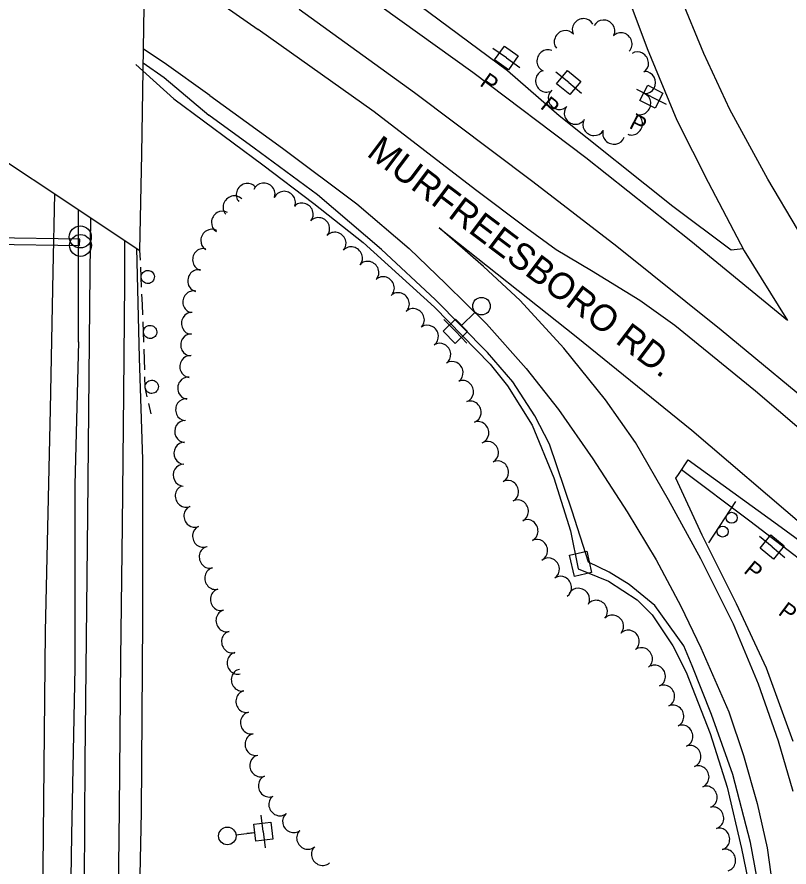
# Model space of a CAD drawing. Extents: x 1746010 to 1754829, y 655801 to 663091.
# Drawn here: x 1754024.1 to 1754375.7, y 656843.1 to 657230 of the extents above; entities that cross this region are included whole.
import ezdxf

# ---------------------------------------------------------------- set-up
doc = ezdxf.new("R2010")
doc.units = 0
for name, color, linetype in [('SURVEY - AERIAL SURVEY - Photo Control - Points - Elevations', 7, 'Continuous'), ('SURVEY - AERIAL SURVEY - Photo Control - Points - Locators', 7, 'Continuous'), ('SURVEY - AERIAL SURVEY - Photo Control - Points - Numbers', 7, 'Continuous'), ('SURVEY - AERIAL SURVEY - Photo Control with Text', 7, 'Continuous'), ('SURVEY - CENTERLINE - Existing Roads Curve Text', 7, 'Continuous'), ('SURVEY - CENTERLINE - Existing Roads Text', 7, 'Continuous'), ('SURVEY - CENTERLINE - Preliminary - Development', 7, 'Continuous'), ('SURVEY - CONTROL - Points - Numbers', 7, 'Continuous')]:
    doc.layers.add(name, color=color, linetype=linetype)

msp = doc.modelspace()

# ---------------------------------------------------------------- linework, layer by layer
at = {"layer": 'SURVEY - AERIAL SURVEY - Photo Control - Points - Elevations'}
for points in [[(1753982.28, 657188.73), (1754080.08, 657123.8), (1754080.93, 657167.72), (1754082.29, 657253.87), (1754084.25, 657323.66), (1754089.74, 657391.89), (1753986.12, 657458.37), (1753985.99, 657391.93), (1753985.12, 657295.57), (1753983.31, 657231.76)], [(1754078.21, 657208.42), (1754095.56, 657192.76), (1754136.12, 657162.67), (1754159.26, 657145.17), (1754181.77, 657127.3), (1754214.2, 657097.87), (1754239.57, 657071.91), (1754247.5, 657062.04), (1754258.73, 657044.18), (1754268.66, 657020.17), (1754276.25, 656996.14), (1754279.63, 656978.75), (1754293.47, 656973.17), (1754306.53, 656964.61), (1754313.35, 656957.81), (1754322.84, 656943.81), (1754328.89, 656931.68), (1754339.84, 656903.89), (1754347.52, 656879.41), (1754354.05, 656851.4), (1754358.17, 656831.58)]]:
    msp.add_lwpolyline(points, dxfattribs=at)
at = {"layer": 'SURVEY - AERIAL SURVEY - Photo Control - Points - Locators'}
for points in [[(1754263.31, 657432.04), (1754270.04, 657378.87), (1754276.75, 657338.19), (1754283.72, 657305.83), (1754290.96, 657277.73), (1754300.49, 657244.28), (1754311.09, 657215.71), (1754324.64, 657183.1), (1754338.91, 657154.83), (1754355.31, 657123.62), (1754374.99, 657091.81), (1754330.98, 657128), (1754283.23, 657165.86), (1754231.77, 657204.81), (1754165.2, 657252.52)], [(1754170.11, 657262.81), (1754207.54, 657235.31), (1754247.49, 657205.62), (1754270.97, 657185.18), (1754322.72, 657143.88), (1754349.35, 657124.09), (1754354.76, 657124.68)], [(1754082.46, 657259.82), (1754102.35, 657246.49), (1754133.89, 657224.33)], [(1754379.5, 657133.43), (1754366.03, 657156.16), (1754348.69, 657187.98), (1754336.85, 657213.49), (1754326.17, 657239.6)], [(1754152.65, 657233.59), (1754205.11, 657195.65), (1754259.01, 657155.1), (1754297.29, 657125.77), (1754344.85, 657087.64), (1754394.72, 657046.26)], [(1754410.66, 657016.7), (1754360.46, 657059.65), (1754323.71, 657089.53), (1754307.82, 657100.92), (1754285.78, 657114.4), (1754269.68, 657123.99), (1754256.08, 657133.86), (1754232.85, 657151.41), (1754186.79, 657186.82), (1754133.89, 657224.33)], [(1754111.99, 657194.33), (1754091.08, 657209.09), (1754081.68, 657215.46)], [(1754081.58, 657209.17), (1754091.13, 657202.56), (1754111.46, 657185.38)], [(1754111.99, 657194.33), (1754145.1, 657170.34), (1754178.83, 657144.95), (1754202.75, 657124.63), (1754219.4, 657108.51), (1754237.98, 657090.35), (1754255.95, 657070.08), (1754270.69, 657051.34), (1754286.3, 657028.95), (1754301.94, 657004.81), (1754315.13, 656982.84), (1754326.39, 656961.76), (1754335.58, 656942.8), (1754348.3, 656913.62), (1754354.99, 656893.8), (1754361.15, 656872.01), (1754365.7, 656851.85), (1754368.96, 656828.87)], [(1754362.13, 656832.88), (1754358.18, 656854.14), (1754350.09, 656885.11), (1754340.4, 656912.46), (1754331.57, 656934.59), (1754327.8, 656943.67), (1754314.58, 656962.06), (1754302.96, 656971.62), (1754293.8, 656977.24), (1754284.39, 656981.85), (1754276.99, 657004.98), (1754266.65, 657035.49), (1754259.96, 657048.43), (1754249.92, 657063.95), (1754238.45, 657077.31), (1754214.63, 657101.48), (1754190.18, 657124.12), (1754161.03, 657149.06), (1754132.18, 657170.31), (1754111.46, 657185.38)], [(1754040.61, 657114.04), (1754041.29, 657149.55)], [(1754057.59, 657138.73), (1754057.29, 657113.76)], [(1754377.63, 656877.42), (1754370.87, 656900.37), (1754361.76, 656926.22), (1754350.36, 656953.57), (1754335.54, 656983.36), (1754320.74, 657010.23), (1754305.77, 657036.26), (1754292.05, 657055.67), (1754273.16, 657079.25), (1754253.25, 657100.99), (1754236.52, 657116.39), (1754216.42, 657134.01), (1754278.8, 657084.62), (1754331.51, 657041.97), (1754382.56, 656998.27)], [(1754073.23, 657109.18), (1754073.22, 657128.35)], [(1754078.6, 657124.78), (1754079.69, 657074.82), (1754081.31, 657028.64), (1754081.24, 656955.57), (1754080.66, 656868.05), (1754078.89, 656781.7)], [(1754031.14, 655808.13), (1754031.3, 655908.75), (1754031.72, 656028.9), (1754031.37, 656137), (1754031.54, 656254.42), (1754031.6, 656339.87), (1754031.41, 656445.55), (1754032.12, 656538.49), (1754033.45, 656650.9), (1754034.71, 656754.09), (1754036.08, 656842.73), (1754037.13, 656950.3), (1754039.4, 657051.48), (1754040.61, 657114.04)], [(1754057.29, 657113.76), (1754056.29, 657003.36), (1754055.05, 656891.08), (1754054.38, 656780.56)], [(1754070.25, 656818.01), (1754070.75, 656869.41), (1754071.43, 656937.85), (1754072.17, 656998.74), (1754072.78, 657058.55), (1754073.23, 657109.18)], [(1754325.34, 657021.8), (1754329.84, 657028.37), (1754370.47, 656999.02), (1754411.6, 656968.94), (1754464.49, 656922.99), (1754497.74, 656893.4)], [(1754377.64, 656900.23), (1754365.43, 656933.5), (1754351.81, 656962.84), (1754336.15, 656994.11), (1754324.18, 657020.03), (1754325.34, 657021.8)], [(1754488.29, 656855.97), (1754482.85, 656857.89), (1754490.99, 656890.46), (1754437.5, 656937.58), (1754399.88, 656968.26), (1754357.83, 657000.5), (1754326.71, 657023.81)]]:
    msp.add_lwpolyline(points, dxfattribs=at)
at = {"layer": 'SURVEY - AERIAL SURVEY - Photo Control - Points - Numbers'}
for points in [[(1754052.19, 657082.05), (1754052.08, 657142.39)], [(1754080.3, 657119.38), (1754080.08, 657123.85)], [(1754080.89, 657106.99), (1754080.45, 657116.18)], [(1754081.27, 657099.1), (1754081.04, 657103.79)], [(1754081.5, 657094.4), (1754081.27, 657099.1)], [(1754081.91, 657082.01), (1754081.65, 657091.21)], [(1754052.19, 657082.1), (1754050.4, 657016.97), (1754050.41, 656933.95), (1754048.92, 656857.56), (1754047.62, 656769.57), (1754047.63, 656692.19), (1754047.02, 656648.26), (1754045.2, 656574.61), (1754044.51, 656529.38), (1754044.63, 656444.15), (1754044.94, 656375.53), (1754044.42, 656301.79), (1754044.34, 656224.86), (1754044.22, 656141.35), (1754043.78, 656087.01), (1754044.06, 656016.26), (1754043.35, 655955.88), (1754042, 655902.52), (1754042.42, 655813.6), (1754042.39, 655808.41)], [(1754082.14, 657074.11), (1754082, 657078.81)], [(1754082.27, 657069.41), (1754082.14, 657074.11)], [(1754083.46, 657057.12), (1754082.5, 657061.31), (1754082.36, 657066.22)], [(1754085.21, 657049.42), (1754084.17, 657054)]]:
    msp.add_lwpolyline(points, dxfattribs=at)
for centre, start, end in [((1754083.67, 657111.68), 295.9972, 295.9832), ((1754084.77, 657086.65), 294.8907, 294.8767), ((1754085.49, 657061.66), 294.8907, 294.8767)]:
    msp.add_arc(centre, 3, start, end, dxfattribs=at)
at = {"layer": 'SURVEY - AERIAL SURVEY - Photo Control with Text'}
for p, q in [((1754052.94, 657129.86), (1754052.94, 657129.86)), ((1754053.04, 657125.99), (1754053.04, 657125.99)), ((1754339.22, 656990.71), (1754351.5, 657009.44))]:
    msp.add_line(p, q, dxfattribs=at)
msp.add_lwpolyline([(1753973.26, 657127.29), (1754052.64, 657126.07), (1754052.68, 657128.89), (1753973.3, 657130.11)], close=True, dxfattribs=at)
for centre, radius in [((1754052.93, 657129.9), 5), ((1754053.03, 657126.03), 5), ((1754349.57, 657002.03), 2.5), ((1754345.46, 656995.76), 2.5)]:
    msp.add_circle(centre, radius, dxfattribs=at)
at = {"layer": 'SURVEY - CENTERLINE - Existing Roads Curve Text'}
for p, q in [((1754246.99, 657211.38), (1754240.87, 657215.72)), ((1754246.99, 657211.38), (1754253.11, 657207.05)), ((1754275.36, 657200.17), (1754269.54, 657204.9)), ((1754275.36, 657200.17), (1754281.18, 657195.43)), ((1754313.06, 657193.7), (1754306.37, 657197.09)), ((1754313.06, 657193.7), (1754319.75, 657190.31)), ((1754232.83, 657095.68), (1754226.57, 657089.65)), ((1754223.76, 657086.94), (1754218.56, 657092.34)), ((1754226.86, 657089.92), (1754229.16, 657092.14)), ((1754223.76, 657086.94), (1754228.97, 657081.54)), ((1754368.03, 656988.76), (1754362.23, 656993.52)), ((1754368.03, 656988.76), (1754373.82, 656984)), ((1754136.3, 656859.19), (1754135.39, 656866.64)), ((1754123.79, 656857.67), (1754132.43, 656858.72)), ((1754132.03, 656858.67), (1754128.85, 656858.29)), ((1754136.3, 656859.19), (1754137.2, 656851.75))]:
    msp.add_line(p, q, dxfattribs=at)
for points in [[(1754246.06, 657216.82), (1754252.43, 657212.31), (1754247.92, 657205.95), (1754241.55, 657210.46)], [(1754274.8, 657205.65), (1754280.85, 657200.73), (1754275.92, 657194.68), (1754269.87, 657199.6)], [(1754311.35, 657198.94), (1754318.3, 657195.41), (1754314.77, 657188.46), (1754307.82, 657191.99)], [(1754218.25, 657087.04), (1754223.86, 657092.45), (1754229.28, 657086.84), (1754223.66, 657081.43)], [(1754367.49, 656994.25), (1754373.52, 656989.3), (1754368.57, 656983.27), (1754362.54, 656988.22)], [(1754140.64, 656855.79), (1754132.9, 656854.85), (1754131.96, 656862.59), (1754139.7, 656863.53)]]:
    msp.add_lwpolyline(points, close=True, dxfattribs=at)
for centre in [(1754235.64, 657098.39), (1754119.92, 656857.2)]:
    msp.add_circle(centre, 4, dxfattribs=at)
at = {"layer": 'SURVEY - CENTERLINE - Existing Roads Text'}
for centre, major_axis in [((1754281.92, 657224.53), (4.45, 2.27)), ((1754291.47, 657223.91), (4.5, -2.18)), ((1754273.64, 657219.02), (3.89, 3.14)), ((1754299.39, 657218.02), (3.58, -3.49)), ((1754265.65, 657210.14), (1.98, 4.59)), ((1754306.94, 657209.23), (2.68, -4.22)), ((1754265, 657200.82), (-1.59, 4.74)), ((1754310.16, 657200.18), (-0.03, -5)), ((1754270.85, 657192.79), (-3.1, 3.92)), ((1754307.99, 657190.5), (-1.89, -4.63)), ((1754278.2, 657186.03), (-3.77, 3.29)), ((1754286.71, 657180.82), (-4.31, 2.53)), ((1754304.21, 657181.25), (-1.89, -4.63)), ((1754295.83, 657176.84), (-4.74, 1.59)), ((1754128.8, 657149.41), (3.62, 3.45)), ((1754136.67, 657149.66), (4.64, -1.87)), ((1754122.84, 657143.74), (3.62, 3.45)), ((1754145.95, 657145.92), (4.64, -1.87)), ((1754154.17, 657140.49), (3.74, -3.32)), ((1754117.45, 657136.73), (2.54, 4.31)), ((1754161.64, 657133.86), (3.74, -3.32)), ((1754112.59, 657128.47), (2.54, 4.31)), ((1754169.12, 657127.22), (3.74, -3.32)), ((1754108.81, 657119.64), (1.12, 4.87)), ((1754176.59, 657120.59), (3.74, -3.32)), ((1754184.07, 657113.95), (3.74, -3.32)), ((1754106.59, 657110), (1.12, 4.87)), ((1754191.12, 657106.91), (3.43, -3.64)), ((1754104.38, 657100.36), (1.12, 4.87)), ((1754197.95, 657099.66), (3.43, -3.64)), ((1754204.78, 657092.4), (3.43, -3.64)), ((1754103.74, 657090.56), (0.18, 5)), ((1754211.25, 657084.84), (2.81, -4.13)), ((1754103.39, 657080.73), (0.18, 5)), ((1754216.88, 657076.58), (2.81, -4.13)), ((1754102.98, 657070.9), (0.48, 4.98)), ((1754222.5, 657068.31), (2.81, -4.13)), ((1754102.02, 657061.09), (0.48, 4.98)), ((1754227.26, 657059.6), (1.75, -4.68)), ((1754101.07, 657051.27), (0.48, 4.98)), ((1754230.75, 657050.23), (1.75, -4.68)), ((1754100.63, 657041.36), (0.17, 5)), ((1754234.25, 657040.87), (1.75, -4.68)), ((1754100.3, 657031.43), (0.17, 5)), ((1754238.64, 657031.9), (2.29, -4.44)), ((1754243.22, 657023.01), (2.29, -4.44)), ((1754099.96, 657021.5), (0.17, 5)), ((1754100.94, 657011.81), (-1.97, 4.59)), ((1754247.8, 657014.13), (2.29, -4.44)), ((1754252.29, 657005.22), (2.19, -4.5)), ((1754104.87, 657002.66), (-1.97, 4.59)), ((1754256.64, 656996.26), (2.19, -4.5)), ((1754108.81, 656993.51), (-1.97, 4.59)), ((1754261, 656987.3), (2.19, -4.5)), ((1754111.84, 656984.04), (-1.27, 4.84)), ((1754266.33, 656978.86), (2.76, -4.17)), ((1754114.38, 656974.4), (-1.27, 4.84)), ((1754271.86, 656970.53), (2.76, -4.17)), ((1754279.99, 656965.18), (4.35, -2.46)), ((1754116.92, 656964.76), (-1.27, 4.84)), ((1754288.13, 656959.65), (3.69, -3.37)), ((1754119.47, 656955.12), (-1.27, 4.84)), ((1754295.51, 656952.9), (3.69, -3.37)), ((1754302.72, 656946), (3, -4)), ((1754122.01, 656945.47), (-1.27, 4.84)), ((1754308.72, 656938.02), (3, -4)), ((1754124.55, 656935.83), (-1.27, 4.84)), ((1754314.69, 656930.02), (2.09, -4.54)), ((1754126.43, 656928.15), (-1.05, 4.89)), ((1754318.88, 656920.94), (2.09, -4.54)), ((1754128.52, 656918.37), (-1.05, 4.89)), ((1754323.06, 656911.86), (2.09, -4.54)), ((1754130.61, 656908.59), (-1.05, 4.89)), ((1754327.13, 656902.74), (1.85, -4.64)), ((1754132.7, 656898.81), (-1.05, 4.89)), ((1754330.83, 656893.47), (1.85, -4.64)), ((1754134.86, 656889.06), (-1.96, 4.6)), ((1754334.53, 656884.2), (1.85, -4.64)), ((1754138.78, 656879.85), (-1.96, 4.6)), ((1754338.23, 656874.93), (1.85, -4.64)), ((1754143.62, 656871.25), (-3.16, 3.88)), ((1754341.26, 656865.43), (1.36, -4.81)), ((1754149.89, 656863.56), (-3.16, 3.88)), ((1754156.32, 656855.98), (-3.38, 3.69)), ((1754343.97, 656855.81), (1.36, -4.81)), ((1754163.08, 656848.61), (-3.38, 3.69)), ((1754346.68, 656846.19), (1.36, -4.81))]:
    msp.add_ellipse(centre, major_axis=major_axis, ratio=0.940188, start_param=0, end_param=3.141593, dxfattribs=at)
at = {"layer": 'SURVEY - CENTERLINE - Preliminary - Development'}
msp.add_line((1754280.78, 656981.11), (1754280.78, 656981.11), dxfattribs=at)
msp.add_lwpolyline([(1754285.8, 656977.13), (1754278, 656975.34), (1754275.77, 656985.08), (1754283.56, 656986.87), (1754285.8, 656977.13)], dxfattribs=at)

# ---------------------------------------------------------------- texts
at = {"layer": 'SURVEY - CENTERLINE - Existing Roads Curve Text'}
for rotation, p in [(324.671, (1754234.46, 657199.06)), (320.8473, (1754262.03, 657188.71)), (333.0951, (1754302.47, 657179.67)), (320.6179, (1754354.65, 656977.35)), (323.4401, (1754370.34, 656958.25))]:
    msp.add_text('P', height=7.48, rotation=rotation, dxfattribs=at).set_placement(p)
at = {"layer": 'SURVEY - CONTROL - Points - Numbers'}
msp.add_text('MURFREESBORO RD.', height=12, rotation=323.024, dxfattribs=at).set_placement((1754182.89, 657167.18))

doc.saveas('drawing.dxf')
